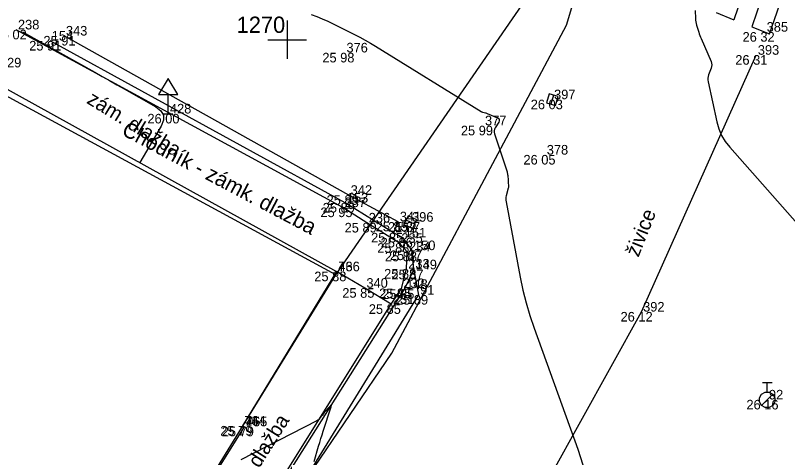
# Model space of a CAD drawing. Extents: x -702257 to -701487, y -1009871 to -1008841.
# Drawn here: x -701782.08 to -701761.96, y -1009385.88 to -1009374.37 of the extents above; entities that cross this region are included whole.
import ezdxf

# ---------------------------------------------------------------- set-up
doc = ezdxf.new("R2010")
doc.units = 0
for name, color, linetype in [('Ex_Major Contours', 7, 'Continuous'), ('Ex_Minor Contours', 7, 'Continuous'), ('Z_body', 7, 'Continuous'), ('Z_body_cisla', 7, 'Continuous'), ('Z_body_vysky_redukovane', 7, 'Continuous'), ('Z_budova', 7, 'Continuous'), ('Z_dopravni_znacky', 7, 'Continuous'), ('Z_hektometricka_sit', 7, 'Continuous'), ('Z_hrany_paty', 7, 'Continuous'), ('Z_katastr_cisla_stavebni', 7, 'Continuous'), ('Z_katastr_hranice', 7, 'Continuous'), ('Z_komunikace', 7, 'Continuous'), ('Z_obruba', 7, 'Continuous'), ('Z_popisy', 7, 'Continuous'), ('Z_rozhranni', 7, 'Continuous'), ('Z_site_kanalizace_znaky', 7, 'Continuous'), ('Z_site_vodovod_znaky', 7, 'Continuous'), ('Z_VDZ12_prerusovana', 7, 'Continuous'), ('Z_vdz_prechod', 7, 'Continuous')]:
    doc.layers.add(name, color=color, linetype=linetype)

# ---------------------------------------------------------------- blocks, each defined once
blk = doc.blocks.new('Z18_1')
for p, q in [((-0.125, 0.45), (0.125, 0.45)), ((0, 0.2), (0, 0.45)), ((-0.2, 0.05), (-0.15, 0.15)), ((-0.2, -0.05), (-0.2, 0.05)), ((-0.15, 0.15), (-0.05, 0.2)), ((0.15, 0.15), (-0.15, -0.15)), ((-0.05, 0.2), (0.05, 0.2)), ((0.05, 0.2), (0.15, 0.15)), ((0.15, 0.15), (0.2, 0.05)), ((0.2, 0.05), (0.2, -0.05)), ((-0.15, -0.15), (-0.2, -0.05)), ((-0.05, -0.2), (-0.15, -0.15)), ((0.05, -0.2), (-0.05, -0.2)), ((0.15, -0.15), (0.05, -0.2)), ((0.2, -0.05), (0.15, -0.15))]:
    blk.add_line(p, q)
blk = doc.blocks.new('Z46260_1')
for p, q in [((0.125, 0.125), (-0.125, 0.125)), ((-0.125, 0.125), (-0.125, -0.125)), ((0.125, 0), (-0.125, 0)), ((0.125, -0.125), (0.125, 0.125)), ((-0.125, -0.125), (0.125, -0.125))]:
    blk.add_line(p, q)
blk = doc.blocks.new('Z527_1')
for p, q in [((0, 0.925), (-0.25, 0.5)), ((0.25, 0.5), (0, 0.925)), ((-0.25, 0.5), (0.25, 0.5)), ((0, 0), (0, 0.5)), ((-0.125, 0), (0.125, 0))]:
    blk.add_line(p, q)
blk = doc.blocks.new('Z18_2')
for p, q in [((-0.125, 0.45), (0.125, 0.45)), ((0, 0.2), (0, 0.45)), ((-0.2, 0.05), (-0.15, 0.15)), ((-0.2, -0.05), (-0.2, 0.05)), ((-0.15, 0.15), (-0.05, 0.2)), ((0.15, 0.15), (-0.15, -0.15)), ((-0.05, 0.2), (0.05, 0.2)), ((0.05, 0.2), (0.15, 0.15)), ((0.15, 0.15), (0.2, 0.05)), ((0.2, 0.05), (0.2, -0.05)), ((-0.15, -0.15), (-0.2, -0.05)), ((-0.05, -0.2), (-0.15, -0.15)), ((0.05, -0.2), (-0.05, -0.2)), ((0.15, -0.15), (0.05, -0.2)), ((0.2, -0.05), (0.15, -0.15))]:
    blk.add_line(p, q)
blk = doc.blocks.new('Z46260_2')
for p, q in [((0.125, 0.125), (-0.125, 0.125)), ((-0.125, 0.125), (-0.125, -0.125)), ((0.125, 0), (-0.125, 0)), ((0.125, -0.125), (0.125, 0.125)), ((-0.125, -0.125), (0.125, -0.125))]:
    blk.add_line(p, q)
blk = doc.blocks.new('Z527_2')
for p, q in [((0, 0.925), (-0.25, 0.5)), ((0.25, 0.5), (0, 0.925)), ((-0.25, 0.5), (0.25, 0.5)), ((0, 0), (0, 0.5)), ((-0.125, 0), (0.125, 0))]:
    blk.add_line(p, q)
blk = doc.blocks.new('POINT_DISPLAY')
blk.add_line((0, 0), (0, 0))

msp = doc.modelspace()

# ---------------------------------------------------------------- linework, layer by layer
at = {"layer": 'Ex_Major Contours'}
for points in [[(-701774.376, -1009374.341), (-701774.229, -1009374.394), (-701774.084, -1009374.451), (-701773.941, -1009374.514), (-701773.801, -1009374.582), (-701773.243, -1009374.863), (-701773.104, -1009374.935), (-701772.967, -1009375.009), (-701772.831, -1009375.087), (-701772.698, -1009375.168), (-701769.947, -1009376.87), (-701769.936, -1009376.877), (-701769.925, -1009376.881), (-701769.913, -1009376.885), (-701769.901, -1009376.888), (-701769.835, -1009376.9), (-701769.827, -1009376.901), (-701769.82, -1009376.904), (-701769.791, -1009376.917), (-701769.52, -1009377.035), (-701769.488, -1009377.055), (-701769.471, -1009377.08), (-701769.471, -1009377.11), (-701769.485, -1009377.144), (-701769.576, -1009377.293), (-701769.594, -1009377.33), (-701769.604, -1009377.369), (-701769.604, -1009377.409), (-701769.595, -1009377.449), (-701769.271, -1009378.437), (-701769.264, -1009378.462), (-701769.258, -1009378.487), (-701769.254, -1009378.512), (-701769.252, -1009378.538), (-701769.243, -1009378.657), (-701769.241, -1009378.692), (-701769.238, -1009378.726), (-701769.233, -1009378.796), (-701769.232, -1009378.813), (-701769.233, -1009378.83), (-701769.235, -1009378.847), (-701769.239, -1009378.864), (-701769.291, -1009379.063), (-701769.299, -1009379.102), (-701769.302, -1009379.141), (-701769.302, -1009379.18), (-701769.296, -1009379.219), (-701768.929, -1009381.18), (-701768.858, -1009381.519), (-701768.774, -1009381.853), (-701768.677, -1009382.184), (-701768.566, -1009382.511), (-701767.426, -1009385.669), (-701767.295, -1009386.076)], [(-701781.9, -1009374.793), (-701780.012, -1009375.848), (-701779.82, -1009375.956), (-701779.629, -1009376.063), (-701779.438, -1009376.171), (-701779.246, -1009376.28), (-701778.42, -1009376.749), (-701778.291, -1009376.848), (-701778.226, -1009376.964), (-701778.224, -1009377.097), (-701778.285, -1009377.248), (-701778.841, -1009378.2)]]:
    msp.add_lwpolyline(points, dxfattribs=at)
at = {"layer": 'Ex_Minor Contours'}
for points in [[(-701764.37, -1009374.237), (-701764.361, -1009374.442), (-701764.358, -1009374.488), (-701764.351, -1009374.533), (-701764.342, -1009374.578), (-701764.329, -1009374.622), (-701764.274, -1009374.798), (-701764.26, -1009374.842), (-701764.244, -1009374.885), (-701764.227, -1009374.928), (-701764.21, -1009374.971), (-701763.955, -1009375.562), (-701763.941, -1009375.606), (-701763.935, -1009375.649), (-701763.939, -1009375.693), (-701763.951, -1009375.736), (-701764.016, -1009375.912), (-701764.03, -1009375.956), (-701764.036, -1009376.001), (-701764.036, -1009376.046), (-701764.03, -1009376.092), (-701763.805, -1009377.134), (-701763.754, -1009377.318), (-701763.68, -1009377.49), (-701763.585, -1009377.652), (-701763.468, -1009377.802), (-701761.111, -1009380.46)], [(-701774.299, -1009385.982), (-701774.181, -1009385.588), (-701774.151, -1009385.489), (-701774.121, -1009385.391), (-701774.09, -1009385.293), (-701774.058, -1009385.195), (-701773.852, -1009384.562), (-701773.844, -1009384.531), (-701773.846, -1009384.518), (-701773.859, -1009384.522), (-701773.882, -1009384.545), (-701774.015, -1009384.693), (-701774.033, -1009384.713), (-701774.05, -1009384.734), (-701774.066, -1009384.754), (-701774.083, -1009384.775), (-701774.147, -1009384.859), (-701774.163, -1009384.879), (-701774.182, -1009384.897), (-701774.203, -1009384.912), (-701774.226, -1009384.926), (-701776.209, -1009385.943)]]:
    msp.add_lwpolyline(points, dxfattribs=at)
at = {"layer": 'Z_budova'}
for p, q in [((-701782.69, -1009376.07), (-701773.71, -1009381.04)), ((-701773.71, -1009381.04), (-701776.16, -1009385.06)), ((-701776.12, -1009385.08), (-701778.5, -1009388.88)), ((-701776.16, -1009385.06), (-701776.12, -1009385.08))]:
    msp.add_line(p, q, dxfattribs=at)
at = {"layer": 'Z_hektometricka_sit'}
for p, q in [((-701775, -1009374.5), (-701775, -1009375.5)), ((-701775, -1009374.5), (-701775, -1009375.5)), ((-701775, -1009374.5), (-701775, -1009375.5)), ((-701775.5, -1009375), (-701774.5, -1009375)), ((-701775.5, -1009375), (-701774.5, -1009375)), ((-701775.5, -1009375), (-701774.5, -1009375))]:
    msp.add_line(p, q, dxfattribs=at)
at = {"layer": 'Z_hrany_paty'}
for p in [(-701771.7, -1009380.99), (-701776.74, -1009390.06)]:
    msp.add_line(p, (-701771.58, -1009381.65), dxfattribs=at)
at = {"layer": 'Z_katastr_hranice'}
for p, q in [((-701767.72, -1009374.62), (-701754.56, -1009329.71)), ((-701773.73, -1009381.12), (-701768.88, -1009374.09)), ((-701772.27, -1009383.16), (-701767.72, -1009374.62)), ((-701773.73, -1009381.12), (-701782.7, -1009376.26)), ((-701777.28, -1009386.88), (-701773.73, -1009381.12)), ((-701783.4, -1009399.55), (-701772.27, -1009383.16))]:
    msp.add_line(p, q, dxfattribs=at)
at = {"layer": 'Z_komunikace'}
for p, q in [((-701773.49, -1009379.25), (-701781.18, -1009375.03)), ((-701772.23, -1009380.03), (-701773.49, -1009379.25)), ((-701771.98, -1009380.16), (-701772.23, -1009380.03)), ((-701771.74, -1009380.49), (-701771.98, -1009380.16)), ((-701771.7, -1009380.99), (-701771.74, -1009380.49)), ((-701771.94, -1009381.5), (-701771.7, -1009380.99)), ((-701777.22, -1009389.85), (-701771.94, -1009381.5))]:
    msp.add_line(p, q, dxfattribs=at)
at = {"layer": 'Z_obruba'}
for p, q in [((-701773.55, -1009379.37), (-701782.06, -1009374.74)), ((-701772.92, -1009379.77), (-701773.55, -1009379.37)), ((-701772.07, -1009380.3), (-701772.92, -1009379.77)), ((-701771.87, -1009380.52), (-701772.07, -1009380.3)), ((-701771.89, -1009380.97), (-701771.87, -1009380.52)), ((-701772.02, -1009381.48), (-701771.89, -1009380.97)), ((-701772.29, -1009381.89), (-701772.02, -1009381.48)), ((-701777.2, -1009389.72), (-701772.29, -1009381.89))]:
    msp.add_line(p, q, dxfattribs=at)
at = {"layer": 'Z_rozhranni'}
for p, q in [((-701773.39, -1009379.05), (-701780.81, -1009374.9)), ((-701773.39, -1009379.05), (-701780.81, -1009374.9)), ((-701772.11, -1009379.74), (-701773.39, -1009379.05)), ((-701772.11, -1009379.74), (-701773.39, -1009379.05)), ((-701772.11, -1009379.74), (-701772.23, -1009380.03)), ((-701772.11, -1009379.74), (-701772.23, -1009380.03)), ((-701772.98, -1009381.47), (-701773.71, -1009381.04)), ((-701772.98, -1009381.47), (-701773.71, -1009381.04)), ((-701772.29, -1009381.89), (-701772.98, -1009381.47)), ((-701772.29, -1009381.89), (-701772.98, -1009381.47))]:
    msp.add_line(p, q, dxfattribs=at)
at = {"layer": 'Z_VDZ12_prerusovana'}
for p, q in [((-701765.77, -1009382.09), (-701762.78, -1009375.4)), ((-701765.77, -1009382.09), (-701762.78, -1009375.4)), ((-701770.91, -1009391.36), (-701765.77, -1009382.09)), ((-701770.91, -1009391.36), (-701765.77, -1009382.09))]:
    msp.add_line(p, q, dxfattribs=at)
at = {"layer": 'Z_vdz_prechod'}
for p, q in [((-701762.041, -1009370.701), (-701763.36, -1009374.478)), ((-701761.577, -1009370.887), (-701762.895, -1009374.663)), ((-701762.43, -1009374.848), (-701761.104, -1009371.05)), ((-701763.824, -1009374.293), (-701763.36, -1009374.478)), ((-701762.895, -1009374.663), (-701762.43, -1009374.848))]:
    msp.add_line(p, q, dxfattribs=at)

# ---------------------------------------------------------------- block references
at = {"layer": 'Z_body'}
for p in [(-701782.06, -1009374.74), (-701762.55, -1009374.8), (-701781.18, -1009375.03), (-701780.81, -1009374.9), (-701773.5, -1009375.34), (-701762.78, -1009375.4), (-701768.09, -1009376.56), (-701778.1, -1009376.93), (-701769.89, -1009377.24), (-701768.28, -1009378), (-701773.39, -1009379.05), (-701773.49, -1009379.25), (-701773.55, -1009379.37), (-701772.92, -1009379.77), (-701772.11, -1009379.74), (-701771.79, -1009379.75), (-701772.23, -1009380.03), (-701771.98, -1009380.16), (-701772.07, -1009380.3), (-701771.74, -1009380.49), (-701771.87, -1009380.52), (-701773.71, -1009381.04), (-701771.89, -1009380.97), (-701771.7, -1009380.99), (-701772.98, -1009381.47), (-701772.02, -1009381.48), (-701771.94, -1009381.5), (-701771.58, -1009381.65), (-701772.29, -1009381.89), (-701765.77, -1009382.09), (-701762.49, -1009384.38), (-701776.16, -1009385.06), (-701776.12, -1009385.08)]:
    msp.add_blockref('POINT_DISPLAY', p, dxfattribs=at)
at = {"layer": 'Z_dopravni_znacky'}
for name in ['Z527_1', 'Z527_2']:
    msp.add_blockref(name, (-701778.1, -1009376.93), dxfattribs=at)
at = {"layer": 'Z_site_kanalizace_znaky'}
for name, p, rotation in [('Z46260_1', (-701768.09, -1009376.56), 73.8), ('Z46260_2', (-701768.09, -1009376.56), 73.8), ('Z46260_1', (-701771.79, -1009379.75), -25.200000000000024), ('Z46260_2', (-701771.79, -1009379.75), -25.200000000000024)]:
    msp.add_blockref(name, p, dxfattribs=dict(at, rotation=rotation))
at = {"layer": 'Z_site_vodovod_znaky'}
for name in ['Z18_1', 'Z18_2']:
    msp.add_blockref(name, (-701762.49, -1009384.38), dxfattribs=at)

# ---------------------------------------------------------------- texts
at = {"layer": 'Z_body_cisla'}
for s, p in [('238', (-701782.015, -1009374.73)), ('343', (-701780.765, -1009374.89)), ('385', (-701762.505, -1009374.79)), ('154', (-701781.135, -1009375.02)), ('376', (-701773.455, -1009375.33)), ('393', (-701762.735, -1009375.39)), ('429', (-701782.485, -1009375.72)), ('397', (-701768.045, -1009376.55)), ('428', (-701778.055, -1009376.92)), ('377', (-701769.845, -1009377.23)), ('378', (-701768.235, -1009377.99)), ('342', (-701773.345, -1009379.04)), ('153', (-701773.445, -1009379.24)), ('237', (-701773.505, -1009379.36)), ('341', (-701772.065, -1009379.73)), ('396', (-701771.745, -1009379.74)), ('236', (-701772.875, -1009379.76)), ('152', (-701772.185, -1009380.02)), ('235', (-701772.025, -1009380.29)), ('151', (-701771.935, -1009380.15)), ('234', (-701771.825, -1009380.51)), ('150', (-701771.695, -1009380.48)), ('43', (-701773.665, -1009381.03)), ('766', (-701773.665, -1009381.03)), ('233', (-701771.845, -1009380.96)), ('149', (-701771.655, -1009380.98)), ('340', (-701772.935, -1009381.46)), ('232', (-701771.975, -1009381.47)), ('148', (-701771.895, -1009381.49)), ('91', (-701771.535, -1009381.64)), ('231', (-701772.245, -1009381.88)), ('392', (-701765.725, -1009382.08)), ('92', (-701762.445, -1009384.37)), ('44', (-701776.115, -1009385.05)), ('764', (-701776.115, -1009385.05)), ('45', (-701776.075, -1009385.07)), ('765', (-701776.075, -1009385.07))]:
    msp.add_text(s, height=0.25, dxfattribs=at).set_placement(p)
at = {"layer": 'Z_body_vysky_redukovane'}
for s, p in [('26 02', (-701782.623, -1009374.99)), ('26 32', (-701763.133, -1009375.05)), ('25 91', (-701781.722, -1009375.28)), ('25 91', (-701781.352, -1009375.15)), ('25 98', (-701774.083, -1009375.59)), ('26 31', (-701763.322, -1009375.65)), ('26 03', (-701768.653, -1009376.81)), ('26 00', (-701778.642, -1009377.18)), ('25 99', (-701770.473, -1009377.49)), ('26 05', (-701768.843, -1009378.25)), ('25 89', (-701773.973, -1009379.3)), ('25 89', (-701774.073, -1009379.5)), ('25 95', (-701774.133, -1009379.62)), ('25 89', (-701773.503, -1009380.02)), ('25 85', (-701772.693, -1009379.99)), ('25 87', (-701772.373, -1009380)), ('25 85', (-701772.813, -1009380.28)), ('25 86', (-701772.563, -1009380.41)), ('25 88', (-701772.653, -1009380.55)), ('25 87', (-701772.323, -1009380.74)), ('25 88', (-701772.453, -1009380.77)), ('25 88', (-701774.293, -1009381.29)), ('25 88', (-701774.293, -1009381.29)), ('25 88', (-701772.473, -1009381.22)), ('25 87', (-701772.283, -1009381.24)), ('25 85', (-701773.563, -1009381.72)), ('25 85', (-701772.603, -1009381.73)), ('25 85', (-701772.523, -1009381.75)), ('25 89', (-701772.163, -1009381.9)), ('25 85', (-701772.873, -1009382.14)), ('26 12', (-701766.312, -1009382.34)), ('26 16', (-701763.032, -1009384.63)), ('25 79', (-701776.743, -1009385.31)), ('25 79', (-701776.743, -1009385.31)), ('25 79', (-701776.703, -1009385.33)), ('25 79', (-701776.703, -1009385.33))]:
    msp.add_text(s, height=0.25, dxfattribs=at).set_placement(p)
at = {"layer": 'Z_katastr_cisla_stavebni'}
msp.add_text('1270', height=0.425, dxfattribs=at).set_placement((-701776.316, -1009374.821))
at = {"layer": 'Z_popisy'}
for s, height, rotation, p in [('zám. dlažba', 0.38, 328.5, (-701780.247, -1009376.638)), ('Chodník - zámk. dlažba', 0.4, 332.1, (-701779.339, -1009377.461)), ('živice', 0.38, 68.4, (-701765.847, -1009380.682)), ('dlažba', 0.38, 57.6, (-701775.73, -1009386.174))]:
    msp.add_text(s, height=height, rotation=rotation, dxfattribs=at).set_placement(p)

doc.saveas('drawing.dxf')
